// Mitsubishi GX Works2 project: 16.自动正反转   PLC: FX3U/FX3UC

PROGRAM MAIN
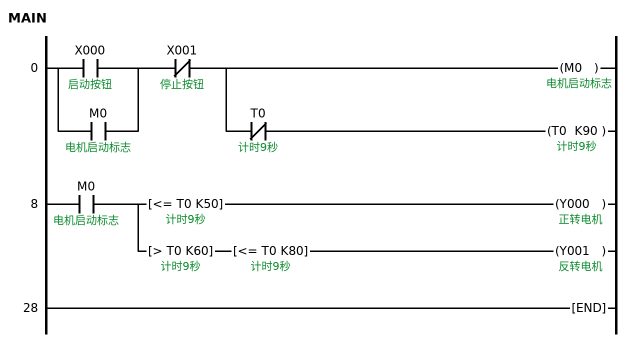
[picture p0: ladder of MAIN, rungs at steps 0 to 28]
0     LD      X000  ; 启动按钮
      OR      M0  ; 电机启动标志
      ANI     X001  ; 停止按钮
      OUT     M0  ; 电机启动标志
      ANI     T0  ; 计时9秒
      OUT     T0 K90  ; 计时9秒
        [note] t0常闭用于T0的循环计时。
8     LD      M0  ; 电机启动标志
      MPS
      AND<=   T0 K50  ; 计时9秒
      OUT     Y000  ; 正转电机
        [note] k90=正转5s停止1s+1s反转2s
      MPP
      AND>    T0 K60  ; 计时9秒
      AND<=   T0 K80  ; 计时9秒
      OUT     Y001  ; 反转电机
28    END
END_PROGRAM

// device comments not shown above
T1  ; 计时2秒
